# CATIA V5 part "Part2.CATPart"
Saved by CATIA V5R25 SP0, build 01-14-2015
Part number: Part2
Bounding box of the stored display mesh (mm): x -8 to 8, y -7.312 to 145, z -7.5 to 7.5
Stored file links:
  D:\kin uygulama8\Part2.CATPart
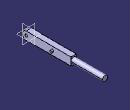
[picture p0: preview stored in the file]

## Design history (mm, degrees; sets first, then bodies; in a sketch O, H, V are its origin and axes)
Body1 (main body)
  Sketch1 on yz-plane, origin (0, 0, 0), H (0, 1, 0), V (0, 0, 1)
    construction line L1 (0, 0) -> (146.8014, 0)
    line L2 (0, 7.5) -> (85, 7.5)
    line L3 (85, -7.5) -> (0, -7.5)
    arc A1 centre (0, 0) radius 7.5 from (0, -7.5) to (0, 7.5) cw
    line L4 (85, 7.5) -> (85, -7.5)
    circle A2 centre (0, 0) radius 2.5
    distance L1 L2 = 7.5
    length L3 = 85
    radius A2 = 2.5
    horizontal: L1 H, L3 H
    tangency: A1 L2, A1 L3
    vertical: L4 V
  Pad1: profile Sketch1, direction (1, 0, 0), length 5, mirrored extent
  Sketch2 on face of Pad1 from Sketch1.L4, origin (0, 85, 0), H (-1, 0, 0), V (0, 0, 1)
    circle A1 centre (0, 0) radius 5
    radius A1 = 5
  Pad2: profile Sketch2, direction (0, 1, 0), length 60
  Sketch3 on end face of Pad1, origin (5, 0, 0), H (0, 1, 0), V (0, 0, 1)
    circle A1 centre (50, 0) radius 2.5
    point P1 (50, 0)
    distance P1 V = 50
    radius A1 = 2.5
    coincidence: P1 H
  Pad3: profile Sketch3, direction (1, 0, 0), length 3
  Mirror1: of Pad3, about yz-plane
